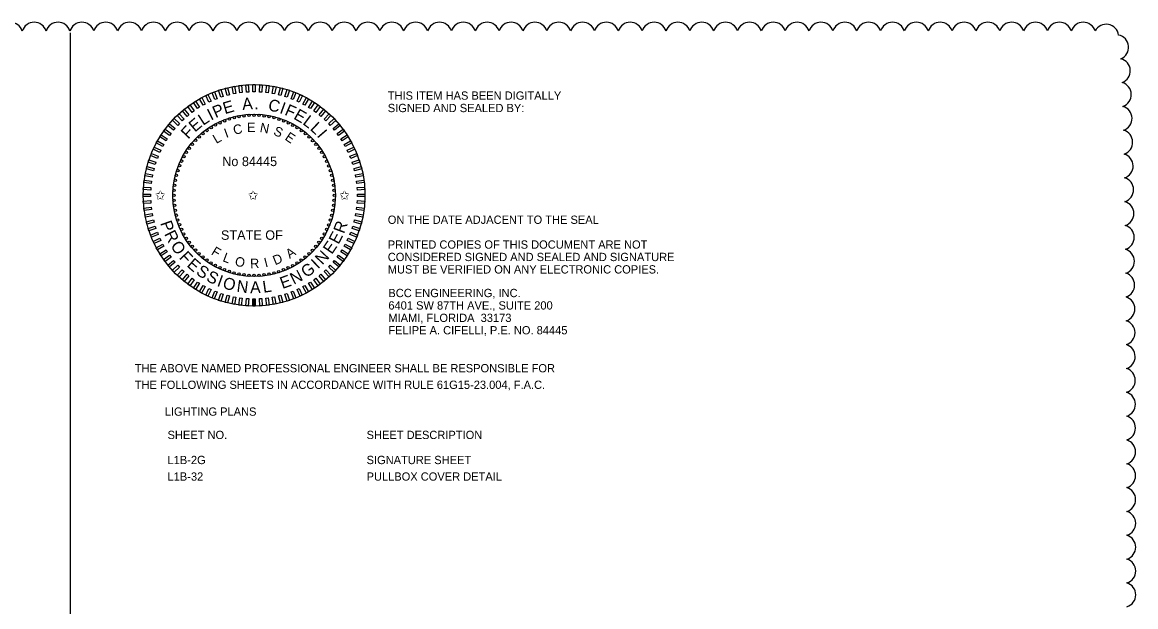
# Model space of a CAD drawing. Extents: x -811.2 to -755.6, y -2295.2 to -2235.1.
# Drawn here: x -777.02 to -767.6, y -2264.84 to -2259.9 of the extents above; entities that cross this region are included whole.
import ezdxf

# ---------------------------------------------------------------- set-up
doc = ezdxf.new("R2010")
doc.units = 0
for name, color, linetype in [('Cloud_dp', 7, 'Continuous'), ('Logo_dp', 7, 'Continuous'), ('NonPlottingEle_dp', 7, 'Continuous'), ('SheetBorder_dp', 7, 'Continuous'), ('TextMisc', 7, 'Continuous'), ('TextNotes', 7, 'Continuous')]:
    doc.layers.add(name, color=color, linetype=linetype)

msp = doc.modelspace()

# ---------------------------------------------------------------- linework, layer by layer
at = {"layer": 'Cloud_dp'}
for centre, radius, start, end in [((-777.1178, -2260.0023), 0.1057, 17.52079, 162.52079), ((-776.9163, -2260.0022), 0.1057, 17.51719, 162.51719), ((-776.7147, -2260.0022), 0.1057, 17.51375, 162.51375), ((-776.5132, -2260.0021), 0.1057, 17.51046, 162.51046), ((-776.3116, -2260.0021), 0.1057, 17.50731, 162.50731), ((-776.1101, -2260.0021), 0.1057, 17.50428, 162.50428), ((-775.9085, -2260.0021), 0.1057, 17.50138, 162.50138), ((-775.707, -2260.0021), 0.1057, 17.5, 162.5), ((-775.5054, -2260.0021), 0.1057, 17.5, 162.5), ((-775.3039, -2260.0021), 0.1057, 17.5, 162.5), ((-775.1023, -2260.0021), 0.1057, 17.5, 162.5), ((-774.9008, -2260.0021), 0.1057, 17.5, 162.5), ((-774.6992, -2260.0021), 0.1057, 17.5, 162.5), ((-774.4977, -2260.0021), 0.1057, 17.5, 162.5), ((-774.2961, -2260.0021), 0.1057, 17.5, 162.5), ((-774.0946, -2260.0021), 0.1057, 17.5, 162.5), ((-773.893, -2260.0021), 0.1057, 17.5, 162.5), ((-773.6915, -2260.0021), 0.1057, 17.5, 162.5), ((-773.4899, -2260.0021), 0.1057, 17.5, 162.5), ((-773.2884, -2260.0021), 0.1057, 17.5, 162.5), ((-773.0868, -2260.0021), 0.1057, 17.5, 162.5), ((-772.8853, -2260.0021), 0.1057, 17.5, 162.5), ((-772.6837, -2260.0021), 0.1057, 17.5, 162.5), ((-772.4822, -2260.0021), 0.1057, 17.5, 162.5), ((-772.2807, -2260.0021), 0.1057, 17.5, 162.5), ((-772.0791, -2260.0021), 0.1057, 17.5, 162.5), ((-771.8776, -2260.0021), 0.1057, 17.5, 162.5), ((-771.676, -2260.0021), 0.1057, 17.5, 162.5), ((-771.4745, -2260.0021), 0.1057, 17.5, 162.5), ((-771.2729, -2260.0021), 0.1057, 17.5, 162.5), ((-771.0714, -2260.0021), 0.1057, 17.5, 162.5), ((-770.8698, -2260.0021), 0.1057, 17.5, 162.5), ((-770.6683, -2260.0021), 0.1057, 17.5, 162.5), ((-770.4667, -2260.0021), 0.1057, 17.5, 162.5), ((-770.2652, -2260.0021), 0.1057, 17.5, 162.5), ((-770.0636, -2260.0021), 0.1057, 17.5, 162.5), ((-769.8621, -2260.0021), 0.1057, 17.5, 162.5), ((-769.6605, -2260.0021), 0.1057, 17.5, 162.5), ((-769.459, -2260.0021), 0.1057, 17.5, 162.5), ((-769.2574, -2260.0021), 0.1057, 17.5, 162.5), ((-769.0559, -2260.0021), 0.1057, 17.5, 162.5), ((-768.8543, -2260.0021), 0.1057, 17.5, 162.5), ((-768.6528, -2260.0021), 0.1057, 17.5, 162.5), ((-768.4512, -2260.0021), 0.1057, 17.5, 162.5), ((-768.2497, -2260.0021), 0.1057, 17.5, 162.5), ((-768.0481, -2260.0021), 0.1057, 17.5, 162.5), ((-767.8535, -2260.0187), 0.1056, 7.70605, 152.70605), ((-767.7706, -2260.108), 0.1057, 293.14506, 78.14506), ((-767.7558, -2260.3074), 0.1057, 290.35349, 75.35349), ((-767.7473, -2260.5083), 0.1057, 289.51862, 74.51862), ((-767.741, -2260.7095), 0.1057, 289.06556, 74.06556), ((-767.736, -2260.9109), 0.1057, 288.76987, 73.76987), ((-767.7319, -2261.1122), 0.1057, 288.55727, 73.55727), ((-767.7285, -2261.3137), 0.1057, 288.39488, 73.39488), ((-767.7255, -2261.5151), 0.1057, 288.2656, 73.2656), ((-767.723, -2261.7166), 0.1057, 288.1595, 73.1595), ((-767.7209, -2261.9181), 0.1057, 288.07039, 73.07039), ((-767.719, -2262.1196), 0.1057, 287.99417, 72.99417), ((-767.7174, -2262.3211), 0.1057, 287.928, 72.928), ((-767.716, -2262.5226), 0.1057, 287.86985, 72.86985), ((-767.7148, -2262.7241), 0.1057, 287.81821, 72.81821), ((-767.7137, -2262.9256), 0.1057, 287.77197, 72.77197), ((-767.7128, -2263.1272), 0.1057, 287.73023, 72.73023), ((-767.7121, -2263.3287), 0.1057, 287.69232, 72.69232), ((-767.7115, -2263.5302), 0.1057, 287.65767, 72.65767), ((-767.711, -2263.7318), 0.1057, 287.62586, 72.62586), ((-767.7106, -2263.9333), 0.1057, 287.5965, 72.5965), ((-767.7103, -2264.1348), 0.1057, 287.56931, 72.56931), ((-767.7101, -2264.3364), 0.1057, 287.54402, 72.54402), ((-767.71, -2264.5379), 0.1057, 287.52043, 72.52043), ((-767.71, -2264.7394), 0.1057, 287.50076, 72.50076)]:
    msp.add_arc(centre, radius, start, end, dxfattribs=at)
at = {"layer": 'Logo_dp'}
for p, q in [((-775.0677, -2262.2978), (-775.0679, -2262.2353)), ((-775.0577, -2262.2978), (-775.0579, -2262.2353)), ((-775.0477, -2262.2978), (-775.0479, -2262.2353))]:
    msp.add_line(p, q, dxfattribs=at)
for points in [[(-775.3184, -2260.525), (-775.3376, -2260.5312), (-775.3569, -2260.4718), (-775.3377, -2260.4656)], [(-775.2654, -2260.5102), (-775.285, -2260.5152), (-775.3005, -2260.4548), (-775.281, -2260.4498)], [(-775.2117, -2260.4989), (-775.2315, -2260.5026), (-775.2432, -2260.4413), (-775.2234, -2260.4375)], [(-775.1573, -2260.4909), (-775.1773, -2260.4934), (-775.1851, -2260.4315), (-775.1651, -2260.4289)], [(-775.1025, -2260.4864), (-775.1226, -2260.4876), (-775.1265, -2260.4253), (-775.1064, -2260.424)], [(-775.0475, -2260.4853), (-775.0677, -2260.4853), (-775.0677, -2260.4228), (-775.0475, -2260.4228)], [(-774.9926, -2260.4876), (-775.0127, -2260.4864), (-775.0088, -2260.4241), (-774.9887, -2260.4253)], [(-774.9379, -2260.4934), (-774.9579, -2260.4909), (-774.9501, -2260.429), (-774.9301, -2260.4315)], [(-774.8837, -2260.5027), (-774.9036, -2260.4989), (-774.8919, -2260.4376), (-774.872, -2260.4413)], [(-774.8302, -2260.5153), (-774.8498, -2260.5103), (-774.8342, -2260.4498), (-774.8147, -2260.4548)], [(-774.7776, -2260.5312), (-774.7968, -2260.525), (-774.7775, -2260.4656), (-774.7583, -2260.4719)], [(-775.518, -2260.616), (-775.535, -2260.6268), (-775.5685, -2260.5741), (-775.5514, -2260.5633)], [(-775.4703, -2260.5886), (-775.488, -2260.5983), (-775.5181, -2260.5436), (-775.5004, -2260.5339)], [(-775.421, -2260.5642), (-775.4393, -2260.5728), (-775.4659, -2260.5163), (-775.4476, -2260.5077)], [(-775.3703, -2260.543), (-775.3891, -2260.5504), (-775.4121, -2260.4923), (-775.3933, -2260.4849)], [(-774.7261, -2260.5505), (-774.7449, -2260.543), (-774.7219, -2260.485), (-774.7031, -2260.4924)], [(-774.6759, -2260.5729), (-774.6942, -2260.5643), (-774.6676, -2260.5078), (-774.6493, -2260.5164)], [(-774.6272, -2260.5984), (-774.6449, -2260.5887), (-774.6148, -2260.534), (-774.5971, -2260.5437)], [(-774.5802, -2260.6269), (-774.5973, -2260.6161), (-774.5638, -2260.5634), (-774.5468, -2260.5742)], [(-775.6076, -2260.6796), (-775.6232, -2260.6925), (-775.663, -2260.6443), (-775.6474, -2260.6315)], [(-775.5638, -2260.6464), (-775.5801, -2260.6583), (-775.6168, -2260.6078), (-775.6005, -2260.5959)], [(-774.5351, -2260.6584), (-774.5515, -2260.6465), (-774.5148, -2260.596), (-774.4984, -2260.6079)], [(-774.4921, -2260.6926), (-774.5076, -2260.6797), (-774.4678, -2260.6316), (-774.4523, -2260.6445)], [(-775.7254, -2260.7947), (-775.7383, -2260.8102), (-775.7864, -2260.7704), (-775.7735, -2260.7549)], [(-775.6886, -2260.7539), (-775.7024, -2260.7686), (-775.7479, -2260.7258), (-775.7341, -2260.7111)], [(-775.6493, -2260.7155), (-775.664, -2260.7293), (-775.7067, -2260.6838), (-775.692, -2260.6699)], [(-774.4513, -2260.7294), (-774.466, -2260.7156), (-774.4232, -2260.6701), (-774.4085, -2260.6839)], [(-774.4128, -2260.7687), (-774.4267, -2260.754), (-774.3812, -2260.7113), (-774.3673, -2260.726)], [(-774.377, -2260.8104), (-774.3898, -2260.7948), (-774.3417, -2260.755), (-774.3289, -2260.7706)], [(-775.791, -2260.8828), (-775.8019, -2260.8999), (-775.8546, -2260.8664), (-775.8438, -2260.8494)], [(-775.7596, -2260.8377), (-775.7715, -2260.8541), (-775.822, -2260.8174), (-775.8101, -2260.801)], [(-774.3438, -2260.8542), (-774.3557, -2260.8379), (-774.3051, -2260.8012), (-774.2933, -2260.8175)], [(-774.3134, -2260.9), (-774.3242, -2260.883), (-774.2715, -2260.8495), (-774.2607, -2260.8666)], [(-775.8196, -2260.9298), (-775.8293, -2260.9475), (-775.884, -2260.9174), (-775.8743, -2260.8997)], [(-774.286, -2260.9477), (-774.2957, -2260.93), (-774.241, -2260.8999), (-774.2313, -2260.9176)], [(-775.8675, -2261.0287), (-775.875, -2261.0475), (-775.933, -2261.0245), (-775.9256, -2261.0057)], [(-775.8451, -2260.9785), (-775.8537, -2260.9968), (-775.9102, -2260.9702), (-775.9016, -2260.9519)], [(-774.2616, -2260.9969), (-774.2702, -2260.9787), (-774.2137, -2260.9521), (-774.2051, -2260.9704)], [(-774.2404, -2261.0477), (-774.2478, -2261.0289), (-774.1897, -2261.0059), (-774.1823, -2261.0247)], [(-775.9027, -2261.1328), (-775.9077, -2261.1524), (-775.9682, -2261.1368), (-775.9632, -2261.1173)], [(-775.8867, -2261.0802), (-775.893, -2261.0994), (-775.9524, -2261.0801), (-775.9461, -2261.0609)], [(-774.2223, -2261.0996), (-774.2286, -2261.0804), (-774.1692, -2261.0611), (-774.163, -2261.0803)], [(-774.2076, -2261.1526), (-774.2126, -2261.133), (-774.1522, -2261.1175), (-774.1471, -2261.137)], [(-775.9153, -2261.1863), (-775.9191, -2261.2062), (-775.9804, -2261.1945), (-775.9766, -2261.1746)], [(-774.1963, -2261.2063), (-774.2, -2261.1865), (-774.1387, -2261.1748), (-774.1349, -2261.1946)], [(-775.9304, -2261.2952), (-775.9316, -2261.3153), (-775.9939, -2261.3114), (-775.9927, -2261.2913)], [(-775.9245, -2261.2405), (-775.9271, -2261.2606), (-775.989, -2261.2527), (-775.9865, -2261.2327)], [(-774.1883, -2261.2607), (-774.1908, -2261.2407), (-774.1289, -2261.2329), (-774.1263, -2261.2529)], [(-774.1837, -2261.3155), (-774.185, -2261.2954), (-774.1227, -2261.2915), (-774.1214, -2261.3116)], [(-775.9327, -2261.3501), (-775.9327, -2261.3703), (-775.9952, -2261.3703), (-775.9952, -2261.3501)], [(-775.9316, -2261.4051), (-775.9304, -2261.4252), (-775.9927, -2261.4291), (-775.994, -2261.409)], [(-774.185, -2261.4254), (-774.1838, -2261.4053), (-774.1214, -2261.4092), (-774.1227, -2261.4293)], [(-774.1827, -2261.3705), (-774.1827, -2261.3503), (-774.1202, -2261.3503), (-774.1202, -2261.3705)], [(-775.9271, -2261.4599), (-775.9246, -2261.4799), (-775.9865, -2261.4877), (-775.989, -2261.4677)], [(-774.1908, -2261.4801), (-774.1883, -2261.4601), (-774.1264, -2261.4679), (-774.1289, -2261.4879)], [(-775.9191, -2261.5143), (-775.9153, -2261.5341), (-775.9767, -2261.5458), (-775.9805, -2261.526)], [(-775.9078, -2261.568), (-775.9027, -2261.5876), (-775.9632, -2261.6031), (-775.9682, -2261.5836)], [(-774.2127, -2261.5878), (-774.2077, -2261.5682), (-774.1472, -2261.5838), (-774.1522, -2261.6033)], [(-774.2001, -2261.5343), (-774.1963, -2261.5144), (-774.135, -2261.5261), (-774.1387, -2261.546)], [(-775.893, -2261.621), (-775.8868, -2261.6402), (-775.9462, -2261.6595), (-775.9524, -2261.6403)], [(-775.875, -2261.673), (-775.8676, -2261.6917), (-775.9256, -2261.7147), (-775.9331, -2261.6959)], [(-774.2479, -2261.6919), (-774.2404, -2261.6731), (-774.1824, -2261.6961), (-774.1898, -2261.7149)], [(-774.2286, -2261.6404), (-774.2224, -2261.6212), (-774.163, -2261.6405), (-774.1693, -2261.6597)], [(-775.8538, -2261.7237), (-775.8452, -2261.7419), (-775.9017, -2261.7685), (-775.9103, -2261.7502)], [(-775.8294, -2261.7729), (-775.8197, -2261.7906), (-775.8744, -2261.8207), (-775.8841, -2261.803)], [(-774.2958, -2261.7908), (-774.2861, -2261.7731), (-774.2314, -2261.8032), (-774.2411, -2261.8209)], [(-774.2703, -2261.7421), (-774.2617, -2261.7238), (-774.2052, -2261.7504), (-774.2138, -2261.7687)], [(-775.802, -2261.8206), (-775.7911, -2261.8376), (-775.8439, -2261.8711), (-775.8547, -2261.854)], [(-775.7716, -2261.8664), (-775.7597, -2261.8827), (-775.8102, -2261.9194), (-775.8221, -2261.9031)], [(-774.3558, -2261.8829), (-774.3439, -2261.8665), (-774.2934, -2261.9032), (-774.3052, -2261.9196)], [(-774.3243, -2261.8378), (-774.3135, -2261.8207), (-774.2608, -2261.8542), (-774.2716, -2261.8712)], [(-775.7384, -2261.9102), (-775.7255, -2261.9258), (-775.7737, -2261.9656), (-775.7865, -2261.95)], [(-775.7025, -2261.9519), (-775.6887, -2261.9666), (-775.7342, -2262.0093), (-775.7481, -2261.9946)], [(-774.4268, -2261.9667), (-774.413, -2261.952), (-774.3675, -2261.9948), (-774.3813, -2262.0095)], [(-774.39, -2261.9259), (-774.3771, -2261.9104), (-774.329, -2261.9502), (-774.3419, -2261.9657)], [(-775.6641, -2261.9912), (-775.6494, -2262.005), (-775.6921, -2262.0505), (-775.7069, -2262.0367)], [(-775.6233, -2262.028), (-775.6078, -2262.0409), (-775.6476, -2262.089), (-775.6631, -2262.0761)], [(-775.5803, -2262.0622), (-775.5639, -2262.0741), (-775.6006, -2262.1246), (-775.617, -2262.1127)], [(-774.5516, -2262.0742), (-774.5353, -2262.0623), (-774.4986, -2262.1129), (-774.5149, -2262.1247)], [(-774.5078, -2262.041), (-774.4922, -2262.0281), (-774.4524, -2262.0763), (-774.468, -2262.0891)], [(-774.4661, -2262.0051), (-774.4514, -2261.9913), (-774.4087, -2262.0368), (-774.4234, -2262.0507)], [(-775.5352, -2262.0937), (-775.5181, -2262.1045), (-775.5516, -2262.1572), (-775.5686, -2262.1464)], [(-775.4882, -2262.1222), (-775.4705, -2262.1319), (-775.5006, -2262.1866), (-775.5182, -2262.1769)], [(-775.4395, -2262.1477), (-775.4212, -2262.1563), (-775.4478, -2262.2128), (-775.4661, -2262.2042)], [(-774.6943, -2262.1564), (-774.6761, -2262.1478), (-774.6495, -2262.2043), (-774.6678, -2262.2129)], [(-774.6451, -2262.132), (-774.6274, -2262.1223), (-774.5973, -2262.177), (-774.615, -2262.1867)], [(-774.5974, -2262.1046), (-774.5804, -2262.0938), (-774.5469, -2262.1465), (-774.564, -2262.1573)], [(-775.3893, -2262.1701), (-775.3705, -2262.1776), (-775.3935, -2262.2356), (-775.4123, -2262.2282)], [(-775.3378, -2262.1894), (-775.3186, -2262.1956), (-775.3379, -2262.255), (-775.3571, -2262.2487)], [(-775.2852, -2262.2053), (-775.2656, -2262.2103), (-775.2811, -2262.2708), (-775.3007, -2262.2658)], [(-775.2317, -2262.2179), (-775.2118, -2262.2217), (-775.2235, -2262.283), (-775.2434, -2262.2793)], [(-775.1775, -2262.2272), (-775.1574, -2262.2297), (-775.1653, -2262.2916), (-775.1853, -2262.2891)], [(-775.1228, -2262.233), (-775.1027, -2262.2342), (-775.1066, -2262.2966), (-775.1267, -2262.2953)], [(-775.0679, -2262.2353), (-775.0477, -2262.2353), (-775.0477, -2262.2978), (-775.0679, -2262.2978)], [(-775.0129, -2262.2342), (-774.9928, -2262.233), (-774.9888, -2262.2953), (-775.009, -2262.2966)], [(-774.9581, -2262.2297), (-774.9381, -2262.2272), (-774.9303, -2262.2891), (-774.9503, -2262.2917)], [(-774.9037, -2262.2217), (-774.8839, -2262.218), (-774.8722, -2262.2793), (-774.892, -2262.2831)], [(-774.8499, -2262.2104), (-774.8304, -2262.2054), (-774.8149, -2262.2658), (-774.8344, -2262.2709)], [(-774.797, -2262.1957), (-774.7778, -2262.1894), (-774.7585, -2262.2488), (-774.7777, -2262.255)], [(-774.745, -2262.1776), (-774.7263, -2262.1702), (-774.7033, -2262.2283), (-774.7221, -2262.2357)]]:
    msp.add_lwpolyline(points, close=True, dxfattribs=at)
for centre in [(-775.3836, -2260.7664), (-775.3456, -2260.7471), (-775.3066, -2260.7302), (-775.2665, -2260.7158), (-775.2256, -2260.704), (-775.1841, -2260.6947), (-775.142, -2260.6881), (-775.0997, -2260.6841), (-775.0571, -2260.6828), (-775.0146, -2260.6842), (-774.9722, -2260.6882), (-774.9302, -2260.6949), (-774.8887, -2260.7043), (-774.8478, -2260.7162), (-774.8078, -2260.7306), (-774.7687, -2260.7476), (-775.4891, -2260.8379), (-775.4554, -2260.8119), (-775.4202, -2260.788), (-774.7308, -2260.7669), (-774.6942, -2260.7886), (-774.659, -2260.8125), (-774.6254, -2260.8387), (-775.5793, -2260.928), (-775.5512, -2260.8961), (-775.521, -2260.8661), (-774.5935, -2260.8668), (-774.5635, -2260.897), (-774.5353, -2260.9289), (-775.6511, -2261.0334), (-775.6294, -2260.9968), (-775.6054, -2260.9616), (-774.5093, -2260.9626), (-774.4854, -2260.9978), (-774.4638, -2261.0344), (-775.6874, -2261.1104), (-775.6704, -2261.0713), (-774.4445, -2261.0724), (-774.4276, -2261.1114), (-775.7231, -2261.2328), (-775.7137, -2261.1913), (-775.7018, -2261.1504), (-774.4132, -2261.1515), (-774.4014, -2261.1924), (-774.3921, -2261.2339), (-775.7338, -2261.3172), (-775.7297, -2261.2748), (-774.3855, -2261.276), (-774.3815, -2261.3183), (-775.7352, -2261.3597), (-775.7339, -2261.4023), (-774.3816, -2261.4034), (-774.3802, -2261.3609), (-775.7299, -2261.4447), (-775.7233, -2261.4867), (-774.3923, -2261.4878), (-774.3856, -2261.4458), (-775.714, -2261.5282), (-775.7022, -2261.5691), (-775.6878, -2261.6092), (-774.428, -2261.6102), (-774.4136, -2261.5702), (-774.4016, -2261.5293), (-775.6709, -2261.6482), (-775.6516, -2261.6862), (-774.4643, -2261.6872), (-774.4449, -2261.6493), (-775.63, -2261.7228), (-775.6061, -2261.7581), (-775.58, -2261.7917), (-774.5361, -2261.7926), (-774.5099, -2261.759), (-774.486, -2261.7238), (-775.5519, -2261.8236), (-775.5219, -2261.8538), (-775.49, -2261.8819), (-774.6263, -2261.8827), (-774.5943, -2261.8545), (-774.5642, -2261.8245), (-775.4564, -2261.9081), (-775.4212, -2261.932), (-775.3846, -2261.9537), (-775.3467, -2261.9731), (-775.3076, -2261.99), (-774.7698, -2261.9735), (-774.7318, -2261.9542), (-774.6952, -2261.9326), (-774.6599, -2261.9087), (-775.2676, -2262.0044), (-775.2267, -2262.0163), (-775.1852, -2262.0257), (-775.1432, -2262.0324), (-775.1008, -2262.0364), (-775.0577, -2262.0378), (-775.0157, -2262.0365), (-774.9733, -2262.0325), (-774.9313, -2262.0259), (-774.8898, -2262.0166), (-774.8489, -2262.0048), (-774.8088, -2261.9904)]:
    msp.add_circle(centre, 0.01, dxfattribs=at)
at = {"layer": 'NonPlottingEle_dp'}
for radius in [0.9375, 0.6875]:
    msp.add_circle((-775.0577, -2261.3603), radius, dxfattribs=at)
at = {"layer": 'SheetBorder_dp'}
msp.add_line((-776.6105, -2269.5845), (-776.6105, -2259.9845), dxfattribs=at)

# ---------------------------------------------------------------- texts
at = {"layer": 'Logo_dp'}
for s, height, rotation, p in [('E', 0.1, 16.54261, (-775.3041, -2260.6746)), ('A', 0.1, 4.42103, (-775.1546, -2260.6381)), ('C', 0.1, 347.7999, (-774.944, -2260.6406)), ('I', 0.1, 26.81606, (-775.4224, -2260.7295)), ('P', 0.1, 23.28287, (-775.3829, -2260.7082)), ('.', 0.1, 356.65403, (-775.0561, -2260.6317)), ('I', 0.1, 340.0631, (-774.8481, -2260.6624)), ('F', 0.1, 336.52991, (-774.8055, -2260.6767)), ('E', 0.1, 330.07956, (-774.7303, -2260.7093)), ('E', 0.1, 40.12142, (-775.5578, -2260.8304)), ('L', 0.1, 33.07918, (-775.4891, -2260.7731)), ('E', 0.08, 0.41861, (-775.1174, -2260.8252)), ('N', 0.08, 349.29143, (-775.013, -2260.8238)), ('L', 0.1, 323.03732, (-774.653, -2260.7544)), ('L', 0.1, 316.7742, (-774.5893, -2260.8022)), ('F', 0.1, 46.57177, (-775.6142, -2260.8899)), ('L', 0.08, 30.40215, (-775.3768, -2260.9267)), ('I', 0.08, 20.01168, (-775.2934, -2260.8762)), ('C', 0.08, 12.20255, (-775.2254, -2260.8487)), ('S', 0.08, 337.02207, (-774.9, -2260.8455)), ('E', 0.08, 325.86633, (-774.8034, -2260.8857)), ('I', 0.1, 310.51108, (-774.5312, -2260.8566)), ('P', 0.1, 289.40551, (-775.8524, -2261.5949)), ('R', 0.1, 69.5134, (-774.2975, -2261.69)), ('R', 0.1, 296.14576, (-775.8194, -2261.6865)), ('E', 0.1, 62.47116, (-774.3437, -2261.7807)), ('O', 0.1, 303.96711, (-775.7679, -2261.7872)), ('E', 0.1, 55.42892, (-774.4006, -2261.8651)), ('F', 0.1, 312.62798, (-775.6955, -2261.8892)), ('F', 0.08, 328.72408, (-775.4257, -2261.8569)), ('L', 0.08, 339.29159, (-775.3284, -2261.916)), ('O', 0.08, 349.68206, (-775.2238, -2261.9557)), ('D', 0.08, 22.01279, (-774.8796, -2261.9522)), ('A', 0.08, 34.49917, (-774.7559, -2261.8997)), ('N', 0.1, 47.17876, (-774.4798, -2261.9542)), ('E', 0.1, 319.07833, (-775.6321, -2261.9575)), ('S', 0.1, 326.12056, (-775.5545, -2262.0234)), ('R', 0.08, 2.33977, (-775.0893, -2261.9776)), ('I', 0.08, 14.20366, (-774.9617, -2261.9709)), ('G', 0.1, 35.11153, (-774.6167, -2262.0618)), ('I', 0.1, 43.64556, (-774.5175, -2261.9886)), ('S', 0.1, 333.193, (-775.4691, -2262.0796)), ('I', 0.1, 340.26543, (-775.3774, -2262.1248)), ('O', 0.1, 343.79863, (-775.3297, -2262.143)), ('E', 0.1, 19.81912, (-774.8174, -2262.1533)), ('N', 0.1, 26.86136, (-774.722, -2262.1179)), ('N', 0.1, 352.45949, (-775.2087, -2262.175)), ('A', 0.1, 0.70966, (-775.0902, -2262.1883)), ('L', 0.1, 8.47665, (-774.978, -2262.1851))]:
    msp.add_text(s, height=height, rotation=rotation, dxfattribs=at).set_placement(p)
for s, p in [('No 84445', (-775.3267, -2261.1131)), ('✩', (-775.8927, -2261.3983)), ('✩', (-775.108, -2261.3983)), ('✩', (-774.3361, -2261.3983)), ('STATE OF', (-775.3374, -2261.7365))]:
    msp.add_text(s, height=0.08, dxfattribs=at).set_placement(p)
at = {"layer": 'TextMisc'}
for s, p in [('THIS ITEM HAS BEEN DIGITALLY', (-773.9272, -2260.5516)), ('SIGNED AND SEALED BY:', (-773.9272, -2260.6566)), ('ON THE DATE ADJACENT TO THE SEAL', (-773.9272, -2261.6016)), ('PRINTED COPIES OF THIS DOCUMENT ARE NOT ', (-773.9272, -2261.8116)), ('CONSIDERED SIGNED AND SEALED AND SIGNATURE ', (-773.9272, -2261.9166)), ('MUST BE VERIFIED ON ANY ELECTRONIC COPIES.', (-773.9272, -2262.0216)), ('BCC ENGINEERING, INC.', (-773.9222, -2262.2215)), ('6401 SW 87TH AVE., SUITE 200', (-773.9222, -2262.3265)), ('MIAMI, FLORIDA  33173', (-773.9222, -2262.4315)), ('FELIPE A. CIFELLI, P.E. NO. 84445', (-773.9222, -2262.5365)), ('THE ABOVE NAMED PROFESSIONAL ENGINEER SHALL BE RESPONSIBLE FOR ', (-776.0663, -2262.8576)), ('THE FOLLOWING SHEETS IN ACCORDANCE WITH RULE 61G15-23.004, F.A.C.', (-776.0663, -2262.9976)), ('LIGHTING PLANS', (-775.8125, -2263.2246))]:
    msp.add_text(s, height=0.07, dxfattribs=at).set_placement(p)
at = {"layer": 'TextNotes'}
for s, p in [('SHEET NO.', (-775.7891, -2263.4216)), ('SHEET DESCRIPTION', (-774.1062, -2263.4216)), ('L1B-2G', (-775.7891, -2263.6338)), ('SIGNATURE SHEET', (-774.1062, -2263.6338)), ('L1B-32', (-775.7891, -2263.7738)), ('PULLBOX COVER DETAIL', (-774.1062, -2263.7738))]:
    msp.add_text(s, height=0.07, dxfattribs=at).set_placement(p)

doc.saveas('drawing.dxf')
